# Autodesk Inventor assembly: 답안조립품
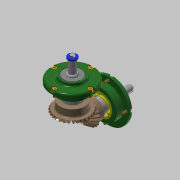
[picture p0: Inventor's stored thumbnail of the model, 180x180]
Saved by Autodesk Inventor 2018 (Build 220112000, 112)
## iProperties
Created: 2021-04
Part Number: 답안조립품
Material: 일반
Document SubType Name: Assembly
Designer: home
Author: home
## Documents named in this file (17)
- C:\Users\home\Desktop\710407V1017\답안조립품.iam
- C:\Users\home\Desktop\710407V1017\본체.ipt
- C:\Users\home\Desktop\710407V1017\커버.ipt
- C:\Users\home\Desktop\710407V1017\볼트 M4 x 10.ipt
- C:\Users\home\Desktop\710407V1017\베어링 6203.ipt
- C:\Users\home\Desktop\710407V1017\오일실 17 x 32 x 8.ipt
- C:\Users\home\Desktop\710407V1017\서브 축.ipt
- 서브 축.ipt
- C:\Users\home\Desktop\710407V1017\키 4 x 4 x 14.ipt
- C:\Users\home\Desktop\710407V1017\서브 베벨기어.ipt
- C:\Users\home\Desktop\710407V1017\메인 축.ipt
- 메인 축.ipt
- C:\Users\home\Desktop\710407V1017\키 5 x 5 x 14.ipt
- C:\Users\home\Desktop\710407V1017\메인 베벨기어.ipt
- C:\Users\home\Desktop\710407V1017\V-벨트풀리.ipt
- C:\Users\home\Desktop\710407V1017\와셔 4 x 16.ipt
- C:\Users\home\Desktop\710407V1017\육각볼트 M4 x 8.ipt
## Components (1 placed, 1 different names)
1. V-벨트풀리:1
